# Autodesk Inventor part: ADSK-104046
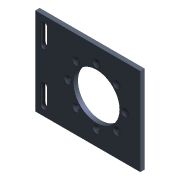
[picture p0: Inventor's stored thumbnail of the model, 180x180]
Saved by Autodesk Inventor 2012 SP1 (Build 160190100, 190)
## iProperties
Shininess: 0.0
Created: 2000-12
Part Number: ADSK-104046
Description: CRS 1/2" THK. x 10" x 12" LONG
Document SubType Name: Modeling
Stock Number: ADSK-104046
Density: 1 g/cm^3
Material: Default
Density: 0.0
Volumn: 0.0
Area: 0.0
PropertySet Name: Model Information
Control State: 0
Master: False
Checked Out: False
Author: gao
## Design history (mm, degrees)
node "Extrusion1" dims "d4" = 12.7, "d5" = 0
  sketch "Sketch1"
    geometry: L1 (703.094, -1328.906)-(398.294, -1328.906); L2 (398.294, -1328.906)-(398.294, -1582.906); L3 (398.294, -1582.906)-(703.094, -1582.906); L4 (703.094, -1582.906)-(703.094, -1328.906); 9 further points
    constraints: 8 end point, 4 coincident, 2 parallel, 1 horizontal, 1 perpendicular
    dimensions: "d0" = 254 distance of L3.end L1.start; "d1" = 304.8 distance of L2.end L3.end; "d2" = 127 distance from line of L3 point (576.094, -1455.906); "d3" = 127 distance from line of L4 point (576.094, -1455.906)
node "Extrusion2" dims "d13" = 12.7, "d14" = 0
  sketch "Sketch3"
    geometry: C1 r 114.998 at (576.094, -1455.906) reference; C2 r 66.675 at (576.094, -1455.906)
    constraints: 1 centre point, 1 coincident
    dimensions: "d12" = 133.35 diameter of C2
node "Extrusion3" dims "d19" = 12.7, "d20" = 0
  sketch "Sketch4"
    geometry: L1 (432.33, -1354.306)-(432.33, -1405.106); L2 (415.058, -1354.306)-(415.058, -1405.106); C1 r 66.675 at (576.094, -1455.906) reference; A1 r 8.636 centre (423.694, -1354.306) between (432.33, -1354.306) and (415.058, -1354.306); A2 r 8.636 centre (423.694, -1405.106) between (415.058, -1405.106) and (432.33, -1405.106)
    constraints: 4 end point, 4 point on circle, 4 tangent, 2 centre point
    dimensions: "d15" = 17.272 diameter of A2; "d16" = 17.272 diameter of A1 (= d15); "d17" = 101.6 vertical distance of A1.centre C1.centre; "d18" = 50.8 distance of A2.centre A1.centre; "d34" = 152.4 horizontal distance of C1.centre A1.centre; "d35" = 152.4 horizontal distance of C1.centre A2.centre (= d34)
node "Rectangular Pattern1" dims "d21" = 20, "d23" = 152.4
node "Hole2" dims "d25" = 11, "d26" = 21.9964, "d27" = 6.35, "d28" = 90 deg, "d29" = 19.05, "d30" = 118 deg
  sketch "Sketch5" dims "d24" = 165.1
    geometry: C1 r 66.675 at (576.094, -1455.906) reference; 2 further points
    constraints: 1 coincident, 1 vertical alignment, 2 other
node "Circular Pattern1" dims "d31" = 80, "d33" = 45 deg
body "Solid1"
